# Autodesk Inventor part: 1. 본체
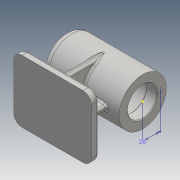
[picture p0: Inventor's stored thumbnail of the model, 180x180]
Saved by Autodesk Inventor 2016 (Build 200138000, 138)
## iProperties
Created: 2020-10
Part Number: 1. 본체
Material: Generic
Document SubType Name: Modeling
Designer: user
Density: 1 g/cm^3
Appearance: Default
Author: user
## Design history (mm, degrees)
sketch "스케치1"
  geometry: L1 (0, 0)-(112, 0); L2 (0, 0)-(0, 34); L3 (0, 34)-(112, 34); L4 (112, 34)-(112, 0); L5 (6, 0)-(6, 10.5); L6 (6, 10.5)-(9, 10.5); L7 (9, 10.5)-(9, 16); L8 (9, 16)-(13, 16); L9 (13, 16)-(13, 17.5); L10 (13, 17.5)-(31, 17.5); L11 (31, 17.5)-(31, 21); L12 (31, 21)-(43, 21); L13 (43, 21)-(43, 24); L14 (43, 24)-(97, 24); L15 (97, 24)-(97, 21); L16 (97, 21)-(112, 21)
  constraints: 32 end point, 9 perpendicular, 4 point on line, 4 vertical, 2 horizontal
  dimensions: "d0" = 112 distance of L1.start L1.end; "d1" = 42 diameter of L16 L1; "d2" = 48 diameter of L14 L1; "d3" = 35 diameter of L10 L1; "d4" = 32 diameter of L8 L1; "d5" = 21 diameter of L6 L1; "d6" = 15 distance of L15.end L16.end; "d7" = 54 distance of L13.end L14.end; "d8" = 12 distance of L11.end L12.end; "d9" = 18 distance of L9.end L10.end; "d10" = 4 distance of L7.end L8.end; "d11" = 3 distance of L5.end L6.end; "d12" = 68 diameter of L3 L1
revolve "회전1" sketch "스케치1" stored, may be unused: angle "d13" = 90 deg
fillet "모깎기1" dims "d14" = 0.3
fillet "모깎기2" dims "d15" = 3
fillet "모깎기3" dims "d16" = 10
chamfer "모따기1" distance "d17" = 1; stored, may be unused: second distance "d18" = 2, angle "d19" = 45 deg
sketch "스케치2"
  geometry: L1 (-45, -64)-(45, -64); L2 (45, -64)-(45, -74); L3 (45, -74)-(-45, -74); L4 (-45, -74)-(-45, -64); 2 further points
  constraints: 8 end point, 2 parallel, 1 horizontal, 1 midpoint, 1 perpendicular, 1 vertical alignment
  dimensions: "d20" = 90 distance of L2.end L3.end; "d21" = 10 distance of L1.end L2.end; "d22" = 74 distance from line of L3 point (0, 0)
extrude "돌출1" join sketch "스케치2" distance "d23" = 112; taper "d24" = 0 deg
sketch "스케치3"
  geometry: L1 (-60, 79)-(-52, 79); L2 (-52, 79)-(-52, 11); L3 (-52, 11)-(-60, 11); L4 (-60, 11)-(-60, 79); L5 (0, 90)-(-112, 90) reference; L6 (0, 90)-(0, 0) reference; 4 further points
  constraints: 8 end point, 3 midpoint, 2 parallel, 1 horizontal, 1 horizontal alignment, 1 perpendicular, 1 vertical alignment
  dimensions: "d25" = 8 distance of L1.start L1.end; "d26" = 68 distance of L1.end L2.end
extrude "돌출2" join sketch "스케치3" stored distance "d27" = 112; taper "d28" = 0 deg
sketch "스케치4"
  geometry: L1 (10, -34)-(112, -34) reference; L2 (112, -64)-(0, -64) reference; L3 (18, -34)-(18, -64); L4 (112, -64)-(0, -64) reference; L5 (0, -64)-(0, -74) reference; 1 further point
  constraints: 2 end point, 2 point on line, 1 perpendicular
  dimensions: "d29" = 18 distance between parallel lines of L3 L5
feature "리브1" sketch "스케치4" dims "d30" = 1, "d31" = 8, "d32" = 0, "d33" = 0, "d34" = 1, "d35" = 1
node "작업 평면1"
fillet "모깎기4" dims "d36" = 12
fillet "모깎기5" dims "d37" = 3
fillet "모깎기6" dims "d38" = 3
sketch "스케치5"
  geometry: 2 further points
  constraints: 1 vertical alignment
  dimensions: "d39" = 26 distance of point (0, 0) point (0, 26)
node "솔리드1"
mirror "대칭1"
